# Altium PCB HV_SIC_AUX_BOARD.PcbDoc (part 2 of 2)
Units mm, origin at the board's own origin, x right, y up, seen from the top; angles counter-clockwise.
Board outline 121.92 x 53.34 mm, 4 copper layers (TOP, GND02, PWR03, BOTTOM), stack 1.6 mm thick; 125 components, 51 nets, 259 pads, 380 vias.
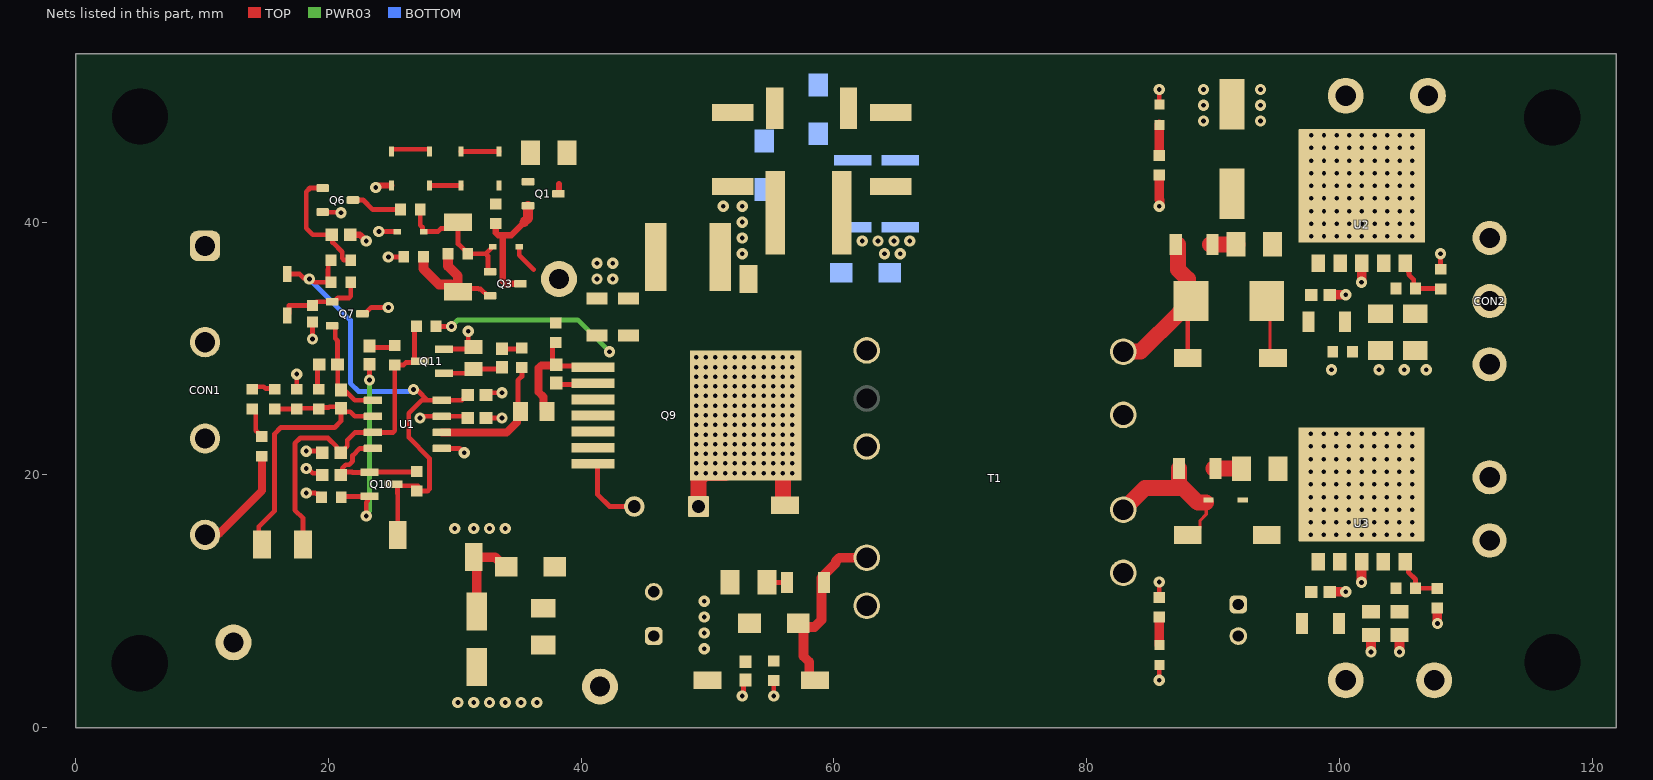
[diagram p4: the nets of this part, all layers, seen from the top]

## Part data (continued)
Q7: library part CMP-013-00100-1, "Small Signal Bipolar Transistor, 0.6A I(C), 60V V(BR)CEO, 1-Element, PNP, Silicon, TO-236AB", Case/Package=SOT23, Max Operating Temperature=150°C, Min Operating Temperature=-65°C, POWER=250mW
Q9: library part CMP-013-00114-3, "1700V 900 M SIC MOSFET", Case/Package="TO-263-7L XL2", Max Operating Temperature=150°C, Min Operating Temperature=-40°C
Q10 Q11: library part CMP-013-00098-1, "Single Bipolar Transistor, NPN, 40 V, 200 mA, 250 mW, TO-236AB (SOT-23), 3 Pins, Surface Mount", Case/Package=SOT23, Max Operating Temperature=150°C, POWER=250mW
R1 R5: library part CMP-009-00047-7, "Fixed Resistor, Metal Glaze/thick Film, 0.1W, 1000000ohm, 75V, 1% +/-Tol, 100ppm/Cel, Surface Mount, 0603", Case/Package=0603, Max Operating Temperature=155°C, Min Operating Temperature=-55°C, POWER=100mW, TOLERANCE=1%, Voltage Rating=75V
R2 R3: library part CMP-009-00313-1, "Fixed Resistor, Metal Glaze/thick Film, 1W, 61.9ohm, 400V, 1% +/-Tol, 100ppm/Cel, Surface Mount, 2010", Case/Package=2010, Max Operating Temperature=155°C, Min Operating Temperature=-55°C, POWER=1W, TOLERANCE=1%
R4: library part CMP-009-00033-7, "Fixed Resistor, Metal Glaze/thick Film, 0.1W, 3900ohm, 75V, 1% +/-Tol, 100ppm/Cel, Surface Mount, 0603", Case/Package=0603, Max Operating Temperature=155°C, Min Operating Temperature=-55°C, POWER=100mW, TOLERANCE=1%, Voltage Rating=75V
R6 R8 R21: library part CMP-009-00009-6, "Fixed Resistor, Metal Glaze/thick Film, 0.1W, 1000ohm, 75V, 1% +/-Tol, 100ppm/Cel, Surface Mount, 0603", Case/Package=0603, Max Operating Temperature=155°C, Min Operating Temperature=-55°C, POWER=100mW, TOLERANCE=1%, Voltage Rating=75V
R7 R10 R18: library part CMP-009-00206-6, "Res SMD 10K Ohm 0.1% 1/10W 0603", Case/Package=0603, Max Operating Temperature=155°C, Min Operating Temperature=-55°C, POWER=100mW, TOLERANCE=0.1%, Voltage Rating=75V
R11 R13: library part CMP-009-00227-4, "Fixed Resistor, Metal Glaze/thick Film, 0.1W, 2490ohm, 75V, 1% +/-Tol, 100ppm/Cel, Surface Mount, 0603", Case/Package=0603, Max Operating Temperature=155°C, Min Operating Temperature=-55°C, POWER=100mW, TOLERANCE=1%, Voltage Rating=75V
R12: library part CMP-009-00039-7, "Fixed Resistor, Metal Glaze/thick Film, 0.1W, 20000ohm, 75V, 1% +/-Tol, 100ppm/Cel, Surface Mount, 0603", Case/Package=0603, Max Operating Temperature=155°C, Min Operating Temperature=-55°C, POWER=100mW, TOLERANCE=1%, Voltage Rating=75V
R15: library part CMP-009-00311-1, "Fixed Resistor, Metal Glaze/thick Film, 0.1W, 40200ohm, 75V, 1% +/-Tol, 100ppm/Cel, Surface Mount, 0603", Case/Package=0603, Max Operating Temperature=155°C, Min Operating Temperature=-55°C, POWER=100mW, TOLERANCE=1%
R16: library part CMP-009-00217-1, "RC Series 0805 0.125 W 10 Ohm ±1% ±100 ppm/°C SMT Thick Film Chip Resistor", Case/Package=0805, Max Operating Temperature=155°C, Min Operating Temperature=-55°C, POWER=125mW, TOLERANCE=1%, Voltage Rating=150V
R17 R23: library part CMP-009-00107-6, "Fixed Resistor, Metal Glaze/thick Film, 0.1W, 15000ohm, 75V, 0.1% +/-Tol, 50ppm/Cel, Surface Mount, 0603", Case/Package=0603, Max Operating Temperature=155°C, Min Operating Temperature=-55°C, POWER=100mW, TOLERANCE=0.1%, Voltage Rating=75V
R19: library part CMP-009-00312-1, "Fixed Resistor, Metal Glaze/thick Film, 0.1W, 324000ohm, 75V, 1% +/-Tol, 100ppm/Cel, Surface Mount, 0603", Case/Package=0603, Max Operating Temperature=155°C, Min Operating Temperature=-55°C, POWER=100mW, TOLERANCE=1%
R20 R41: library part CMP-009-00034-7, "Fixed Resistor, Metal Glaze/thick Film, 0.1W, 4020ohm, 75V, 1% +/-Tol, 100ppm/Cel, Surface Mount, 0603", Case/Package=0603, Max Operating Temperature=155°C, Min Operating Temperature=-55°C, POWER=100mW, TOLERANCE=1%, Voltage Rating=75V
R22: library part CMP-009-00032-7, "Fixed Resistor, Metal Glaze/thick Film, 0.1W, 3300ohm, 75V, 1% +/-Tol, 100ppm/Cel, Surface Mount, 0603", Case/Package=0603, Max Operating Temperature=155°C, Min Operating Temperature=-55°C, POWER=100mW, TOLERANCE=1%, Voltage Rating=75V
R24: library part CMP-009-00027-8, "Fixed Resistor, Metal Glaze/thick Film, 0.1W, 2000ohm, 75V, 1% +/-Tol, 100ppm/Cel, Surface Mount, 0603", Case/Package=0603, Max Operating Temperature=155°C, Min Operating Temperature=-55°C, POWER=100mW, TOLERANCE=1%, Voltage Rating=75V
R25 R26: library part CMP-009-00314-4, "Fixed Resistor, Metal Glaze/thick Film, 0.75W, 1.8ohm, 200V, 1% +/-Tol, 100ppm/Cel, Surface Mount, 1206", Case/Package=1206, Max Operating Temperature=155°C, Min Operating Temperature=-55°C, POWER=750mW, TOLERANCE=1%, Voltage Rating=200V
R27: library part CMP-009-00216-1, "Res Pulse Withstand Thick Film 0805 120 Ohm 1% 1/3W ±100ppm/°C Molded Paper T/R", Case/Package=0805, Max Operating Temperature=155°C, Min Operating Temperature=-55°C, POWER=330mW, TOLERANCE=1%
R30 R31 R42: library part CMP-009-00232-4, "Fixed Resistor, Metal Glaze/thick Film, 0.1W, 56000ohm, 75V, 1% +/-Tol, 100ppm/Cel, Surface Mount, 0603", Case/Package=0603, Max Operating Temperature=155°C, Min Operating Temperature=-55°C, POWER=100mW, TOLERANCE=1%, Voltage Rating=75V
R32 R33 R34: library part CMP-009-00080-4, "Fixed Resistor, Metal Glaze/thick Film, 1W, 150000ohm, 500V, 1% +/-Tol, 100ppm/Cel, Surface Mount, 2512", Case/Package=2512, Max Operating Temperature=155°C, Min Operating Temperature=-55°C, POWER=1W, TOLERANCE=1%, Voltage Rating=500V
R35 R36 R37: library part CMP-009-00345-1, "Fixed Resistor, Metal Glaze/thick Film, 0.25W, 100ohm, 200V, 1% +/-Tol, 100ppm/Cel, Surface Mount, 1206", Case/Package=1206, Max Operating Temperature=155°C, Min Operating Temperature=-55°C, POWER=250mW, TOLERANCE=1%, Voltage Rating=200V
R38 R39: library part CMP-009-00090-7, "Fixed Resistor, Metal Glaze/thick Film, 0.25W, 0ohm, 200V, 5% +/-Tol, 100ppm/Cel, Surface Mount, 1206", Case/Package=1206, Max Operating Temperature=155°C, Min Operating Temperature=-55°C, POWER=250mW, TOLERANCE=5%, Voltage Rating=200V
R40: library part CMP-009-00347-1, "Fixed Resistor, Metal Glaze/thick Film, 0.1W, 76800ohm, 75V, 1% +/-Tol, 100ppm/Cel, Surface Mount, 0603", Case/Package=0603, Max Operating Temperature=155°C, Min Operating Temperature=-55°C, POWER=100mW, TOLERANCE=1%
R43: library part CMP-009-00017-6, "Chip Resistor, 10 KOhm, +/- 1%, 01 W, -55 to 155 degC, 0603 (1608 Metric)", Case/Package=0603, Max Operating Temperature=155°C, Min Operating Temperature=-55°C, POWER=100mW, TOLERANCE=1%, Voltage Rating=50V
T1: library part CMP-012-00012-1, "TRANSFORMERS PQ2020 1.6.2mH 115:7:6::6:3"
TP1 TP2 TP3 TP4 TP6 TP7 TP8 TP9 TP10 TP11 TP12 TP14 TP20 TP21: library part CMP-017-000000-3, "HARWIN - S1751-46R - PCB Test Point, S1751 Series, Surface Mount, Brass, Tin Plated Contacts"
TP5 TP13 TP15 TP16 TP17 TP18 TP19: library part CMP-017-000005-3, "Test Point MultiPurpose THM .445 L .125 OD Heat Resistant Nylon 46 White"
U1: library part CMP-00024-00042-4, "Automotive, 30-V, low-power current-mode PWM controller, 16-V/12.5-V UVLO for SiC, 100% duty cycle 8-SOIC -40 to 150", Case/Package=SOIC8, Max Operating Temperature=150°C, Min Operating Temperature=-40°C
U2 U3: library part CMP-019-00117-2, "LDO Regulator Pos 1.5V to 16V 2A 6-Pin(5+Tab) HRP Tape", Case/Package=HRP5, Max Operating Temperature=105°C, Max Supply Voltage=32V, Min Operating Temperature=-40°C, Output Current 1=2A

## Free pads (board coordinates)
  oval 3.962x3.962 hole 4.445 unplated: M1(5.085,5.1) M1(5.089,48.36) M1(116.845,48.28) M1(116.849,5.18)

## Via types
v1: diameter 0.889, hole 0.356, TOP to BOTTOM, tented both sides, 162 vias
v2: diameter 0.635, hole 0.356, TOP to BOTTOM, tented both sides, 143 vias
v3: diameter 0.889, hole 0.381, TOP to BOTTOM, tented both sides, 75 vias

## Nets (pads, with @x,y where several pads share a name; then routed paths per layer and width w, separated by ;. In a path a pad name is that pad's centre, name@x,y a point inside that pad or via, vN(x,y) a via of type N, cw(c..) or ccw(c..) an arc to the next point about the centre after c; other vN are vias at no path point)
COMP: C23.2 C25.2 Q7.2 U1.1 | length 8.4
  TOP w0.381: Q7.2@20.3,31.8 20.439,31.8 20.548,31.691 20.548,30.799 20.726,30.622 C23.2@20.726,28.75 ; C23.2@20.704,28.772 20.75,28.726 20.75,26.976 C25.2@21,26.726 20.988,26.714 21.039,26.663 21.337,26.663 22.095,25.905 U1.1@23.525,25.905
CS: C27.2 Q11.3 R20.2 R21.1 TP14.1 U1.3 | length 28.1
  TOP w0.381: TP14.1@18,14.5 18,16.579 17.361,17.218 17.361,22.498 17.783,22.92 19.965,22.92 20.663,22.222 20.663,22.039 20.702,22 20.976,22 C27.2@20.976,21.75 ; C27.2@21.101,21.875 21.125,21.875 21.289,22.039 21.289,22.063 21.5,22.274 21.5,22.75 22.115,23.365 U1.3@23.525,23.365 25.111,23.365 25.25,23.504 R20.2@25.25,28.697 25.554,28.697 25.946,28.697 26.139,28.891 26.74,28.891 26.816,28.966 Q11.3@26.816,29 ; R21.1@26.973,31.75 26.816,31.593 Q11.3@26.816,29 ; Q11.3@27.25,29 Q11.3@26.816,29
FB: C25.1 R17.2 R19.1 R22.2 TP12.1 U1.2 | length 24.3
  TOP w0.381: TP12.1@14.75,14.5 14.5,14.75 14.5,15.906 15.75,17.156 15.75,23.25 16.25,23.75 20.5,23.75 21,24.25 C25.1@21,25.274 ; R17.2@15.75,25.223 R22.2@17.5,25.223 17.548,25.271 19.202,25.271 R19.1@19.25,25.223 19.364,25.337 20.039,25.337 20.101,25.399 20.875,25.399 21.275,24.999 21.727,24.999 22.091,24.635 U1.2@23.525,24.635
HV_IN: C1.1 C2.1 C32.1 CON1.1 D1.2 Q1.3 R34.1 T1.1 TP2.1 | length 0.8
  TOP w0.508: Q1.3@38.2,42.25 38.204,42.25 38.25,42.296 38.25,43
  other v3: 52.75,37.5 52.75,38.75 52.75,40 51.25,41.25 52.75,41.25
NetC1_2: C1.2 D3.1 Q1.1 R1.2
NetC13_1: C13.1 C14.1 C30.1 D14.1 R38.1 TP4.1 U2.1 U2.2 | length 4.6
  TOP w0.254: D14.1@94.5,33.75 94.5,29.5 TP4.1@94.75,29.25
NETC15_1: C15.1 D9.2 Q7.1 R12.1 | length 7.2
  TOP w0.381: D9.2@16.75,32.6 16.9,32.749 16.9,33.4 18.775,33.4 19.075,33.7 20.5,33.7 20.61,33.809 20.61,33.861 20.749,34 21.637,34 21.777,34.139 R12.1@21.777,35.25
NETC16_2: C16.2 Q6.1 R10.2 | length 9.4
  TOP w0.381: 19.485,39 18.773,39 18.25,39.523 18.25,42.398 18.552,42.7 Q6.1@19.55,42.7 ; 19.548,39 C16.2@20.274,39 20.337,38.937 20.337,38.398 21.097,37.638 21.097,37.139 21.237,37 R10.2@21.777,37
NETC17_1: C17.1 C18.1 C31.1 D18.1 R39.1 TP8.1 U3.1 U3.2
NETC23_1: C23.1 R19.2 | length 2.1
  TOP w0.381: R19.2@19.25,26.777 19.137,26.89 19.137,28.613 C23.1@19.274,28.75
NETC24_2: C24.2 Q9.1 R16.2 R18.1 | length 10.4
  TOP w0.381: Q9.1@40.932,28.512 40.825,28.619 38.141,28.619 C24.2@38.034,28.726 38.02,28.739 37.75,28.739 R18.1@37.75,30.234 ; R18.1@37.75,30.234 R18.1@37.989,30.473 ; R18.1@37.75,30.234 R18.1@37.989,30.473 ; R18.1@37.989,30.473 R18.1@38,30.473 R18.1@37.989,30.473
  TOP w0.635: R16.2@37.3,25 37.029,25.271 37.029,26.163 36.648,26.544 36.648,28.441 36.88,28.673 C24.2@37.75,28.673
NETC26_1: C26.1 Q10.2 R23.1 | length 16
  TOP w0.381: R23.1@21.027,18.25 21.077,18.3 23.09,18.3 Q10.2@23.2,18.3 ; v3(23,16.75) 23,17.837 23.09,17.927 23.09,18.191 Q10.2@23.2,18.3 ; v3(23.25,27.5) C26.1@23.25,28.75 ; Q10.2@23.265,18.3 Q10.2@23.2,18.3
  PWR03 w0.381: v3(23,16.75) 23,16.887 23.25,17.137 v3(23.25,27.5)
NETC26_2: C26.2 R20.1 | length 2.4
  TOP w0.381: C26.2@23.25,30.202 C26.2@23.262,30.202 ; C26.2@23.262,30.214 23.4,30.076 R20.1@25.076,30.076 ; R20.1@25.076,30.076 R20.1@25.25,30.25 R20.1@25.076,30.076
NETC28_1: C28.1 R24.1 | length 1.6
  TOP w0.381: C28.1@33.75,29.976 33.75,29.952 35.211,29.952 R24.1@35.313,30.053
NETC28_2: C28.2 Q11.1 R27.1 | length 5
  TOP w0.381: Q11.1@29.15,28.05 31.176,28.05 31.513,28.387 C28.2@33.613,28.387 ; C28.2@33.613,28.387 C28.2@33.75,28.524 C28.2@33.613,28.387
NetC29_2: C29.2 R37.2 | length 1.9
  TOP w0.381: C29.2@54.551,11.5 R37.2@56.475,11.5
NetC30_2: C30.2 R35.2 | length 2.2
  TOP w1.27: R35.2@89.775,38.229 91.928,38.229 C30.2@91.949,38.25
NetC31_2: C31.2 R36.2 | length 2.4
  TOP w1.27: C31.2@92.254,20.5 R36.2@90.2,20.5 ; R36.2@90.2,20.5 90.025,20.5 R36.2@90.2,20.5
NetC32_2: C32.2 D6.1 R2.1 R3.1 R32.2
  other v3: 64,37.5 65.25,37.5 62.25,38.5 63.5,38.5 64.75,38.5 66,38.5
NetD1_1: D1.1 D2.2
NetD2_1: D2.1 R2.2 R3.2
NetD3_2: D3.2 D5.1 | length 3
  TOP w0.381: D5.1@30.5,45.6 D3.2@33.5,45.6
NetD4_2: D4.2 R37.1 T1.5 TP1.1 | length 14.3
  TOP w0.762: D4.2@57.175,8.25 57.2,8.25 57.594,7.856 57.594,5.651 58.051,5.194 58.051,4.068 58.368,3.75 TP1.1@58.5,3.75 ; D4.2@57.594,7.968 58.25,7.968 ; 58.468,7.968 59.025,8.525 59.025,11.875 60.147,12.997 60.147,13.147 60.45,13.45 T1.5@62.6,13.45
NetD5_2: D5.2 D7.1 | length 2.5
  TOP w0.381: D7.1@28,42.9 D5.2@30.5,42.9
NetD6_2: D6.2 J2.1 Q9.8 T1.3 TP10.1 | length 8.5
  TOP w0.381: Q9.8@54.727,24.246 Q9.8@54.727,24.721
  TOP w1.27: J2.1@49.29,17.5 49.29,19.684 49.755,20.149 v2(51.392,20.149) ; Q9.8@52.827,24.712 Q9.8@53.678,24.712 ; v2(55.964,20.149) 55.964,17.654 56.028,17.59 TP10.1@56.134,17.59
  other v2: 49.106,20.149 49.868,20.149 50.63,20.149 52.154,20.149 52.916,20.149 53.678,20.149 54.44,20.149 55.202,20.149 56.726,20.149 49.106,20.911 49.868,20.911 50.63,20.911 51.392,20.911 52.154,20.911 52.916,20.911 53.678,20.911 54.44,20.911 55.202,20.911 55.964,20.911 56.726,20.911 49.106,21.673 49.868,21.673 50.63,21.673 51.392,21.673 52.154,21.673 52.916,21.673 53.678,21.673 54.44,21.673 55.202,21.673 55.964,21.673 56.726,21.673 49.106,22.435 49.868,22.435 50.63,22.435 51.392,22.435 52.154,22.435 52.916,22.435 53.678,22.435 54.44,22.435 55.202,22.435 55.964,22.435 56.726,22.435 49.106,23.197 49.868,23.197 50.63,23.197 51.392,23.197 52.154,23.197 52.916,23.197 53.678,23.197 54.44,23.197 55.202,23.197 55.964,23.197 56.726,23.197 49.106,23.959 49.868,23.959 50.63,23.959 51.392,23.959 52.154,23.959 52.916,23.959 53.678,23.959 54.44,23.959 55.202,23.959 55.964,23.959 56.726,23.959 49.106,24.721 49.868,24.721 50.63,24.721 51.392,24.721 52.154,24.721 52.853,24.721 53.678,24.721 54.44,24.721 55.202,24.721 55.964,24.721 56.726,24.721 49.106,25.483 49.868,25.483 50.63,25.483 51.392,25.483 52.154,25.483 52.916,25.483 53.678,25.483 54.44,25.483 55.202,25.483 55.964,25.483 56.726,25.483 49.106,26.245 49.868,26.245 50.63,26.245 51.392,26.245 52.154,26.245 52.916,26.245 53.678,26.245 54.44,26.245 55.202,26.245 55.964,26.245 56.726,26.245 49.106,27.007 49.868,27.007 50.63,27.007 51.392,27.007 52.154,27.007 52.916,27.007 53.678,27.007 54.44,27.007 55.202,27.007 55.964,27.007 56.726,27.007 49.106,27.769 49.868,27.769 50.63,27.769 51.392,27.769 52.154,27.769 52.916,27.769 53.678,27.769 54.44,27.769 55.202,27.769 55.964,27.769 56.726,27.769 49.106,28.531 49.868,28.531 50.63,28.531 51.392,28.531 52.154,28.531 52.916,28.531 53.678,28.531 54.44,28.531 55.202,28.531 55.964,28.531 56.726,28.531 49.106,29.293 49.868,29.293 50.63,29.293 51.392,29.293 52.154,29.293 52.916,29.293 53.678,29.293 54.44,29.293 55.202,29.293 55.964,29.293 56.726,29.293
NetD7_2: D7.2 D10.1 | length 3.3
  TOP w0.381: D10.1@25,45.6 25,45.752 25.01,45.762 27.99,45.762 28,45.752 D7.2@28,45.6
NetD8_1: D8.1 D13.1 Q3.1 R5.2 R7.2 TP20.1 | length 11.6
  TOP w0.381: R7.2@27.277,41 27.277,39.767 27.45,39.593 27.45,39.285 D13.1@27.485,39.25 ; D13.1@27.555,39.25 28.669,39.25 28.911,39.492 29.742,39.492 TP20.1@30.25,40 30.25,38.25 30.303,38.25 31.027,37.527 R5.2@31.027,37.5 32.466,37.5 32.895,37.929 32.895,38.022 32.93,38.057 D8.1@33,38.057 ; 32.443,37.5 32.633,37.31 32.633,36.175 32.743,36.065 Q3.1@32.8,36.065
NetD14_2: D14.2 R35.1 T1.14 TP3.1 | length 15.2
  TOP w0.381: TP3.1@88,29.25 D14.2@88,32.81
  TOP w1.27: T1.14@82.9,29.75 84.25,29.75 87.31,32.81 87.51,32.81 87.655,32.955 87.655,33.155 D14.2@88.25,33.75 ; R35.1@87.225,38.229 87.225,36.254 87.785,35.694 ; D14.2@88,33.75 88,34.315 88,35.5
NetD18_2: D18.2 R36.1 T1.10 TP7.1 | length 12.4
  TOP w0.254: TP7.1@88,15.25 88.399,15.25 88.971,15.821 88.971,16.386 89.458,16.873 D18.2@89.458,17.808
  TOP w1.27: T1.10@82.9,17.25 84.625,18.975 87.2,18.975 ; R36.1@87.3,20.5 87.3,19.308 88.8,17.808 D18.2@89.458,17.808
NetDS1_2: DS1.2 R4.1 | length 2.5
  TOP w0.762: R4.1@85.75,45.277 DS1.2@85.75,47.75
NetDS2_2: DS2.2 R8.1 | length 2.2
  TOP w0.762: DS2.2@85.751,6.531 85.75,6.532 85.75,8.702 R8.1@85.75,8.75
NetQ1_2: Q1.2 Q3.3 R1.1 | length 10.1
  TOP w0.508: R1.1@33.25,39.887 33.25,39.159 33.436,38.973 33.803,38.973 ; Q3.3@35.2,35.115 34.365,35.115 34.304,35.055 34.065,35.055 33.808,35.312 33.808,37.14 33.803,37.145 33.803,38.973 ; 35.5,40 34.473,38.973 33.803,38.973
  TOP w0.762: 35.5,40 35.8,40.3 Q1.2@35.8,41.3
NetQ3_2: Q3.2 R5.1 R6.2 TP21.1 | length 10.8
  TOP w0.381: TP21.1@30.25,34.5 30.5,34.75 31.85,34.75 31.903,34.697 32.068,34.697 32.6,34.165 Q3.2@32.8,34.165
  TOP w0.762: R6.2@27.527,37.25 27.527,36.299 28.758,35.067 29.723,35.067 29.723,34.817 30.041,34.5 TP21.1@30.25,34.5 30.25,35.744 29.473,36.521 R5.1@29.473,37.5
NETQ6_3: Q6.3 R7.1 | length 4.1
  TOP w0.381: Q6.3@21.95,41.75 22.757,41.75 23.511,40.996 24.68,40.996 24.684,41 R7.1@25.723,41
NetR11_1: R11.1 R13.2 | length 2.5
  TOP w0.381: R13.2@14,25.223 14.025,25.223 14.264,24.984 14.264,23.513 14.484,23.292 14.484,23.266 14.723,23.027 R11.1@14.75,23.027
NETR13_1: R13.1 R17.1 | length 1.9
  TOP w0.381: R13.1@14,26.777 14.203,26.98 14.891,26.98 15.046,26.825 15.702,26.825 R17.1@15.75,26.777
NETR16_1: R16.1 R24.2 U1.6 | length 10.9
  TOP w0.381: R16.1@35,25.2 35,27.484 35.313,27.796 R24.2@35.313,28.5
  TOP w0.635: U1.6@28.975,23.365 34.115,23.365 34.917,24.167 34.917,24.717 R16.1@35.2,25 R16.1@35,25.2
NetR32_1: R32.1 R33.2
NetR33_1: R33.1 R34.2
NetR40_2: R40.2 R41.1 U2.5 | length 4.3
  TOP w0.381: U2.5@105.22,36.75 105.461,36.509 105.461,36.039 105.5,36 105.5,35.839 105.885,35.454 105.885,34.892 R40.2@106.027,34.75 107.973,34.75 R41.1@108,34.723
NetR42_2: R42.2 R43.1 U3.5 | length 4.2
  TOP w0.381: U3.5@105.19,13.125 105.456,12.859 105.456,12.294 106.027,11.723 R42.2@106.027,11.03 106.657,11.03 106.66,11.027 R43.1@107.75,11.027
PGND: C2.2 C5.2 C6.2 C7.2 C8.2 C9.2 C15.2 C16.1 C21.1 C22.1 C27.1 CON1.2 CON1.3 D8.2 D10.2 Q6.2 Q7.3 Q11.2 R22.1 R23.2 R25.2 R26.2 R27.2 R31.1 T1.6 TP5.1 TP13.1 TP15.1 U1.5 | length 26.8
  TOP w0.381: R22.1@17.5,26.777 v3(17.5,27.973) ; v3(18.25,18.578) 18.942,18.578 19.005,18.516 19.234,18.516 19.473,18.277 R23.2@19.473,18.25 ; v3(18.25,20.513) 18.387,20.513 18.773,20.127 19.397,20.127 C21.1@19.524,20 ; v3(18.25,21.88) 19.394,21.88 C27.1@19.524,21.75 ; v3(18.75,30.75) C15.2@18.75,32.1 ; Q6.2@19.55,40.8 19.575,40.775 20.975,40.775 v3(21,40.75) ; Q7.3@22.7,32.75 22.9,32.75 23.4,33.25 v3(24.75,33.25) ; U1.5@28.975,22.095 30.405,22.095 v3(30.75,21.75) ; Q11.2@29.15,29.95 31.324,29.95 R27.2@31.5,30.126 ; v3(31.066,31.374) 31.066,30.489 R27.2@31.428,30.126 ; C8.2@32.476,24.5 v3(33.75,24.5) ; C22.1@32.476,26.338 32.638,26.5 v3(33.75,26.5) ; D8.2@35.11,38.057 35.11,37.39 36.25,36.25 ; v3(52.75,2.5) 52.847,2.597 52.847,3.614 C6.2@53.007,3.774 ; v3(55.25,2.5) R31.1@55.25,3.723
  TOP w0.508: C16.1@21.726,39 22.5,39 v3(23,38.5) ; v3(23.75,42.75) 23.853,42.75 24.003,42.9 D10.2@25,42.9
  TOP w0.762: C9.2@36.737,6.55 C9.2@36.986,6.301
  other v3: 30.25,2 31.5,2 32.75,2 34,2 35.25,2 36.5,2 41.25,35.5 42.5,35.5 41.25,36.75 42.5,36.75
RT/CT: C21.2 Q10.1 R15.2 U1.4 | length 9.7
  TOP w0.381: C21.2@20.976,20 21.1,20.124 21.1,20.527 21.379,20.807 21.644,20.807 21.924,21.087 21.924,21.526 22.493,22.095 U1.4@23.525,22.095 ; C21.2@21.213,20.237 21.887,20.237 21.924,20.2 Q10.1@23.265,20.2 23.6,20.2 23.638,20.238 26.962,20.238 R15.2@27,20.277
S1_GND: C11.2 C12.2 C13.2 C14.2 CON2.2 CON2.3 DS1.1 R30.1 R41.2 T1.12 TP17.1 U2.3 U2.6 | length 5.3
  TOP w0.381: DS1.1@85.75,49.25 v3(85.75,50.5) ; R41.2@108,36.277 v3(108,37.5)
  TOP w0.762: C14.2@99.226,34.25 v3(100.5,34.25) ; v3(101.75,35.25) 101.765,35.265 101.765,36.735 U2.3@101.78,36.75
  other v1: 97.78,38.875 98.78,38.875 99.78,38.875 100.78,38.875 101.78,38.875 102.78,38.875 103.78,38.875 104.78,38.875 105.78,38.875 97.78,39.875 98.78,39.875 99.78,39.875 100.78,39.875 101.78,39.875 102.78,39.875 103.78,39.875 104.78,39.875 105.78,39.875 97.78,40.875 98.78,40.875 99.78,40.875 100.78,40.875 101.78,40.875 102.78,40.875 103.78,40.875 104.78,40.875 105.78,40.875 97.78,41.875 98.78,41.875 99.78,41.875 100.78,41.875 101.78,41.875 102.78,41.875 103.78,41.875 104.78,41.875 105.78,41.875 97.78,42.875 98.78,42.875 99.78,42.875 100.78,42.875 101.78,42.875 102.78,42.875 103.78,42.875 104.78,42.875 105.78,42.875 97.78,43.875 98.78,43.875 99.78,43.875 100.78,43.875 101.78,43.875 102.78,43.875 103.78,43.875 104.78,43.875 105.78,43.875 97.78,44.875 98.78,44.875 99.78,44.875 100.78,44.875 101.78,44.875 102.78,44.875 103.78,44.875 104.78,44.875 105.78,44.875 97.78,45.875 98.78,45.875 99.78,45.875 100.78,45.875 101.78,45.875 102.78,45.875 103.78,45.875 104.78,45.875 105.78,45.875 97.78,46.875 98.78,46.875 99.78,46.875 100.78,46.875 101.78,46.875 102.78,46.875 103.78,46.875 104.78,46.875 105.78,46.875
  other v3: 99.373,28.321 103.127,28.321 105.127,28.321 106.873,28.321 89.25,48 93.75,48 89.25,49.25 93.75,49.25 89.25,50.5 93.75,50.5
S2_GND: C17.2 C18.2 C19.1 C20.1 CON3.2 DS2.1 R43.2 T1.8 TP19.1 U3.3 U3.6 | length 8.1
  TOP w0.381: v3(85.75,3.75) 85.75,4.973 DS2.1@85.77,4.993
  TOP w0.762: C18.2@99.226,10.75 v3(100.5,10.75) ; v3(101.75,11.5) U3.3@101.75,13.125 ; v3(102.5,6) C20.1@102.5,7.325 ; v3(104.75,6) C19.1@104.75,7.325 ; v3(107.75,8.25) R43.2@107.75,9.5
  other v1: 97.75,15.25 98.75,15.25 99.75,15.25 100.75,15.25 101.75,15.25 102.75,15.25 103.75,15.25 104.75,15.25 105.75,15.25 97.75,16.25 98.75,16.25 99.75,16.25 100.75,16.25 101.75,16.25 102.75,16.25 103.75,16.25 104.75,16.25 105.75,16.25 97.75,17.25 98.75,17.25 99.75,17.25 100.75,17.25 101.75,17.25 102.75,17.25 103.75,17.25 104.75,17.25 105.75,17.25 97.75,18.25 98.75,18.25 99.75,18.25 100.75,18.25 101.75,18.25 102.75,18.25 103.75,18.25 104.75,18.25 105.75,18.25 97.75,19.25 98.75,19.25 99.75,19.25 100.75,19.25 101.75,19.25 102.75,19.25 103.75,19.25 104.75,19.25 105.75,19.25 97.75,20.25 98.75,20.25 99.75,20.25 100.75,20.25 101.75,20.25 102.75,20.25 103.75,20.25 104.75,20.25 105.75,20.25 97.75,21.25 98.75,21.25 99.75,21.25 100.75,21.25 101.75,21.25 102.75,21.25 103.75,21.25 104.75,21.25 105.75,21.25 97.75,22.25 98.75,22.25 99.75,22.25 100.75,22.25 101.75,22.25 102.75,22.25 103.75,22.25 104.75,22.25 105.75,22.25 97.75,23.25 98.75,23.25 99.75,23.25 100.75,23.25 101.75,23.25 102.75,23.25 103.75,23.25 104.75,23.25 105.75,23.25
S_1: C11.1 C12.1 CON2.1 R4.2 R30.2 R38.2 R40.1 TP16.1 U2.4 | length 2.5
  TOP w0.762: v3(85.75,41.25) 85.774,41.274 v3@85.774,41.364 ; R4.2@85.75,43.723 85.75,41.784 85.775,41.759 v3@85.775,41.365
S_2: C19.2 C20.2 CON3.1 R8.2 R39.2 R42.1 TP18.1 U3.4 | length 1.2
  TOP w0.381: R8.2@85.74,10.313 v3@85.74,11.517
  other v3: 85.75,11.527
SRC: C24.1 J2.2 Q9.2 Q9.3 Q9.4 Q9.5 Q9.6 Q9.7 R18.2 R21.2 R25.1 R26.1 | length 23.8
  TOP w0.381: R21.2@28.527,31.75 v3(29.75,31.75) ; C24.1@38.006,27.156 40.772,27.156 40.858,27.242 Q9.2@40.932,27.242 ; Q9.7@40.932,20.892 41.104,20.892 41.294,20.702 41.294,18.456 42.25,17.5 J2.2@44.21,17.5
  PWR03 w0.381: v3@29.818,31.818 30.263,32.263 39.737,32.263 v3(42.25,29.75)
V_P_aux: C5.1 C6.1 C9.1 C29.1 CON1.4 D4.1 D11.2 R11.2 R31.2 TP11.1 | length 8.7
  TOP w0.635: CON1.4@10.25,15.26 10.372,15.382 11.382,15.382 14.75,18.75 R11.2@14.75,21.473
  other v3: 49.75,6.25 49.75,7.5 49.75,8.75 49.75,10
VDD: C7.1 C8.1 D11.1 D13.2 R6.1 TP6.1 U1.7 | length 13.6
  TOP w0.381: v3(24,39.25) D13.2@25.445,39.25 ; v3(24.75,37.25) R6.1@25.973,37.25 ; v3(27.25,24.5) 27.387,24.5 27.522,24.635 30.889,24.635 C8.1@31.024,24.5
  TOP w0.762: TP6.1@31.21,13.29 31.21,12.883 31.317,12.776 31.471,12.776 31.75,12.497 C7.1@31.75,9.553 ; TP6.1@31.421,13.5 33.2,13.5 33.95,12.75 D11.1@34.075,12.75
  other v3: 30,15.75 31.5,15.75 32.75,15.75 34,15.75
VREF: C22.2 D9.1 Q10.3 R10.1 R12.2 R15.1 TP9.1 U1.8 | length 41.6
  TOP w0.381: D9.1@16.75,35.9 17.712,35.9 18.028,35.585 18.415,35.585 v3(18.5,35.5) 18.637,35.5 18.887,35.25 R12.2@19.973,35.25 ; R10.1@20.223,37 19.992,36.769 19.992,36.296 19.973,36.278 R12.2@19.973,35.25 ; Q10.3@25.165,19.25 25.362,19.25 25.471,19.141 25.471,18.503 25.5,18.474 TP9.1@25.5,15.25 ; Q10.3@25.5,19.25 25.609,19.141 27.091,19.141 27.091,18.815 R15.1@27,18.723 27.861,18.723 28,18.863 28,21.324 26.361,22.963 26.361,24.868 27.398,25.905 27.845,25.905 ; v3(26.75,26.75) 26.847,26.653 27.097,26.653 27.845,25.905 ; C22.2@31.024,26.338 31,26.338 30.711,26.05 30.711,26.044 30.572,25.905 U1.8@28.975,25.905 27.845,25.905 ; R12.2@19.973,35.25 R12.2@20.223,35.25 R12.2@19.973,35.25
  BOTTOM w0.381: v3(18.5,35.5) 21.75,32.25 21.75,27.25 22.389,26.611 26.357,26.611 26.398,26.653 26.653,26.653 v3(26.75,26.75)
pads on no net: T1.2

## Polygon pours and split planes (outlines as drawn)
V_P_aux on TOP "NONET_L-01_P-001" (solid, pour order 72): 35,15 53.75,15 53.75,10 56.5,10 56.5,0 35,0
PGND on TOP "PGND_L01_P056" (solid, pour order 56): 36,32.879 46.5,32.879 46.5,40.25 46,40.75 38.75,40.75 36,38
HV_IN on TOP "NONET_L-01_P-001" (solid, pour order 50): 50,33.75 50,44 50.5,44.5 56,44.5 56,36.75 54.75,35.5 54.75,34.25 54.25,33.75
NetC1_2 on TOP "NONET_L-01_P-001" (solid, pour order 53): 32.25,41 34.5,41 34.5,42 35.75,42 36.75,43 36.75,47 32.25,47
HV_IN on TOP "NONET_L-01_P-001" (solid, pour order 73): 41,44 41,53.34 13.34,53.34 7.75,47.75 7.75,37 8.75,36 11.75,36 12.25,36.5 12.25,42.5 18,48.25 36.5,48.25 37.25,47.5 37.25,41.5 39.5,41.5 39.5,42.5
VDD on TOP "NONET_L-01_P-001" (solid, pour order 81): 28.5,10 28.5,16.75 35.25,16.75 35.25,10
PGND on TOP "PGND_L01_P071" (solid, pour order 71): 28.496,7.823 38.623,7.823 38.623,0 28.496,0
NETC17_1 on TOP "NETC17_1_L01_P067" (solid, pour order 67): 90.805,22 90.805,6.5 99.5,6.5 99.5,18.923 96.52,18.923 96.52,22
SRC on TOP "SRC_L01_P065" (solid, pour order 65): 40.25,31.5 40.25,32 39.5,32.75 36.5,32.75 36.5,31.25 38.5,31.25 39,30.75 39,20.13 43.18,20.13 45.25,22.2 45.25,31.5
NetD6_2 on TOP "NETD6_2_L01_P063" (solid, pour order 63): 48.895,29.655 49.53,30.29 55.88,30.29 56.515,29.655 56.515,19.495 55.88,18.86 49.53,18.86 48.895,19.495
NetC13_1 on TOP "NETC13_1_L01_P069" (solid, pour order 69): 89,31 96.25,31 96.25,30.25 98.75,30.25 98.75,33.75 101.5,33.75 101.5,38.5 97.25,38.5 97.25,45 89,45
S1_GND on TOP "S1_GND_L01_P068" (solid, pour order 68): 89.5,52.25 93.5,52.25 94.5,51.25 94.5,47.5 93.5,46.5 89.25,46.5 88.5,47.25 88.5,51.25
NetC32_2 on TOP "NONET_L-01_P-001" (solid, pour order 51): 57.75,44.75 57.75,36.5 65.25,36.5 66.5,37.75 66.5,44.75
NetR33_1 on TOP "NONET_L-01_P-001" (solid, pour order 58): 49.5,48 49.5,49.5 51.5,51.5 55.5,51.5 56.25,50.75 56.25,47.25 50.25,47.25
NetR32_1 on TOP "NONET_L-01_P-001" (solid, pour order 52): 66.75,45.75 59.75,45.75 59.75,50.75 60.25,51.25 65,51.25 66.75,49.5
S_2 on TOP "S_2_L01_P070" (solid, pour order 70): 96.613,24.498 96.613,20.248 96.613,0 109,0 114.25,5.25 114.25,24.498
S_1 on TOP "S_1_L01_P061" (solid, pour order 61): 101.5,38.5 101.5,33.5 99,33.5 99,26.75 110.25,26.75 113,26.75 113.75,27.5 113.75,38.5
S1_GND on TOP "NONET_L-01_P-001" (solid, pour order 59): 98.627,30.691 100.377,30.691 100.377,28.941 102.377,28.941 102.377,31.691 108.377,31.691 108.377,27.441 98.627,27.441
PGND on GND02 "PGND_L02_P075" (solid, pour order 75): 8.255,48.26 13.335,53.34 59.66,53.34 63.5,49.5 63.5,34.75 44.25,34.75 44.25,18 59.69,18 64.25,18 64.25,5.75 58.5,0 14.25,0 8.255,5.995
S2_GND on GND02 "S2_GND_L02_P082" (solid, pour order 82): 81,20.5 81,5.75 86.75,0 109,0 114.046,5.046 114.046,18.542 114.046,21.954 111.75,24.25 84.75,24.25
HV_IN on GND02 "NONET_L-01_P-001" (solid, pour order 64): 51.75,40.5 53.5,40.5 54.25,39.75 54.25,35.25 56.25,33.25 62.25,33.25 64.5,31 64.5,29 64,28.5 61,28.5 58.5,31 54.75,31 51,34.75 51,39.75
NetD6_2 on GND02 "NONET_L-01_P-001" (solid, pour order 74): 48.25,30 48.25,19.25 64,19.25 64.5,19.75 64.5,23.5 58.5,23.5 57.5,24.5 57.5,30
S1_GND on GND02 "S1_GND_L02_P079" (solid, pour order 79): 80.899,25.25 80.899,23.351 81.75,22.5 84.25,22.5 85.242,23.492 85.242,24.492 86,25.25 111.5,25.25 113.665,27.415 113.665,38.989 113.665,50.038 109.703,54 85.242,54 80.899,49.657 80.899,38.862
NetC32_2 on BOTTOM "NONET_L-01_P-001" (solid, pour order 77): 59.75,40.25 66.5,40.25 66.5,35.25 65.75,34.5 63.25,34.5 63.25,37.5 59.75,37.5
NetD2_1 on BOTTOM "NONET_L-01_P-001" (solid, pour order 76): 57.25,48.584 59.916,48.584 62.25,46.25 67.25,46.25 67.25,43.5 57.25,43.5
NetD6_2 on BOTTOM "NONET_L-01_P-001" (solid, pour order 60): 55.25,32.75 55.25,29.75 48.75,29.75 48.5,29.5 48.5,20.25 49,19.75 57.5,19.75 57.5,31.25 61,34.75 61,37.25 58.75,37.25 58.75,36.25
NetD1_1 on BOTTOM "NONET_L-01_P-001" (solid, pour order 78): 56.275,48.525 56.275,45.775 52.775,45.775 52.775,50.525 54.775,52.525 60.025,52.525 60.025,48.525
HV_IN on BOTTOM "NONET_L-01_P-001" (solid, pour order 57): 53.25,44.25 55.25,44.25 55.25,41 53.25,41 53.25,36.75 50.75,36.75 50.75,41.75
V_P_aux on PWR03 "NONET_L-01_P-001" (solid, pour order 66): 8.25,18 8.25,6 14.25,0 58.5,0 64.25,5.75 64.25,16.5 59.75,16.5 15,16.5 13.5,18
HV_IN on PWR03 "NONET_L-01_P-001" (solid, pour order 80): 15.25,36 15.25,41.75 20.25,46.75 43.75,46.75 49,41.5 49,33.75 58.75,33.75 60.75,31.75 60.75,28.25 64.25,28.25 64.25,37 64.25,53.34 13.34,53.34 8.25,48.25 8.25,36
S_2 on PWR03 "S_2_L03_P062" (solid, pour order 62): 81,20.5 81,5.75 86.75,0 109,0 114.046,5.046 114.046,18.542 114.046,21.954 111.75,24.25 84.75,24.25
VDD on PWR03 "NONET_L-01_P-001" (solid, pour order 49): 31.5,40.75 31.5,18 33,16.5 35,16.5 35,14.75 29.25,14.75 24.25,19.75 24.25,40.75
NetD6_2 on PWR03 "NONET_L-01_P-001" (solid, pour order 54): 48.25,30 48.25,19.25 64,19.25 64.5,19.75 64.5,23.5 58.5,23.5 57.5,24.5 57.5,30
S_1 on PWR03 "S_1_L03_P055" (solid, pour order 55): 80.899,25.25 80.899,23.351 81.75,22.5 84.25,22.5 85.242,23.492 85.242,24.492 86,25.25 111.5,25.25 113.665,27.415 113.665,38.989 113.665,50.038 110.363,53.34 84.582,53.34 80.899,49.657 80.899,38.862

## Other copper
BOTTOM:
  region net S2_GND: 106.22,14.625 97.22,14.625 97.22,23.875 106.22,23.875
  region net S1_GND: 106.25,38.25 97.25,38.25 97.25,47.5 106.25,47.5

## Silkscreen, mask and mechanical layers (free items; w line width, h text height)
Top Overlay:
  drawing of 58 lines, arcs and shapes, not listed
  text "25W HV SIC AUX EVAL BOARD" at 17,50.75 h2
  text "DNP" at 51.7,49.95 h0.75
  text "KIT-CRD-025DD17P-J Rev. '.revision'" at 17,49 h1.91
  text "S1_GND" at 108.928,40.25 h1 r270
  text "HV" at 12.75,38.75 h1 r270
  text "DNP" at 84.2,37.95 h0.75
  text "S1_GND" at 108.928,35.25 h1 r270
  text "P_GND" at 12.678,32 h1 r270
  text "S_1" at 108.928,29.5 h1 r270
  text "DNP" at 96.75,26.25 h0.75
  text "P_GND" at 12.678,25 h1 r270
  text "DNP" at 100.95,24.2 h0.75
  text "DNP" at 90.2,22.95 h0.75
  text "S2_GND" at 108.928,22.25 h1 r270
  text "V_P_Aux" at 12.678,16.999 h1 r270
  text "S2" at 108.761,15.5 h1 r270
  text "DNP" at 54.45,13.45 h0.75
Bottom Solder:
  region: 48.5,19.75 48.5,29.74 57.5,29.74 57.5,19.75
OUTLINE:
  the board outline again, w0.254
Route Tool Path:
  lines w0.1: 48,33.375 ccw(c48.5,33.375) 49.001,33.375 ; 57.499,37.125 ccw(c58,37.125) 58.5,37.125
  lines w0.2: 0,0 0,0 ; 0,0 0,53.34 ; 0,0 121.92,0 ; 0,53.34 0,53.34 ; 0,53.34 121.92,53.34 ; 121.92,0 121.92,53.34 ; 121.92,0 121.92,0 ; 121.92,53.34 121.92,53.34
  lines w1: 46.75,15.5 46.75,19.5 ; 48.5,33.375 48.5,40.625 ; 58,37.125 58,44.375 ; 64.347,24.302 60.603,24.302 60.6,24.299 60.6,27.8 64.35,27.8 ; 64.35,27.8 64.35,27.8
